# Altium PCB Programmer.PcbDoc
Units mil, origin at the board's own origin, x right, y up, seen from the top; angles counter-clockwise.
Board outline 2400 x 1200 mil, 2 copper layers (Top Layer, Bottom Layer); 47 components, 42 nets, 160 pads, 0 vias.
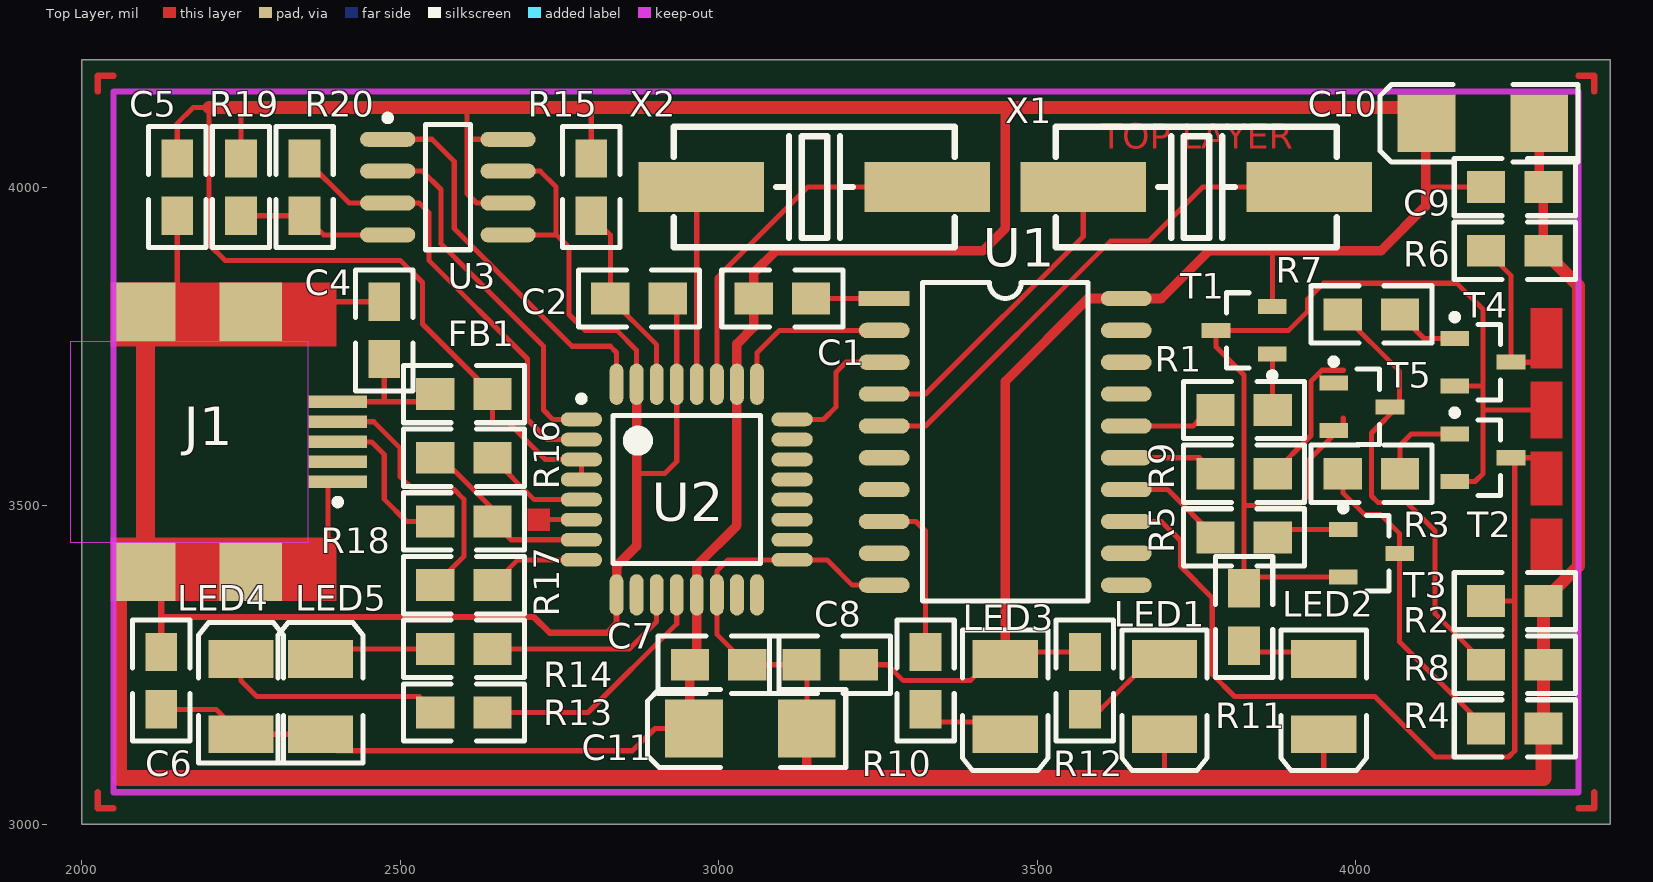
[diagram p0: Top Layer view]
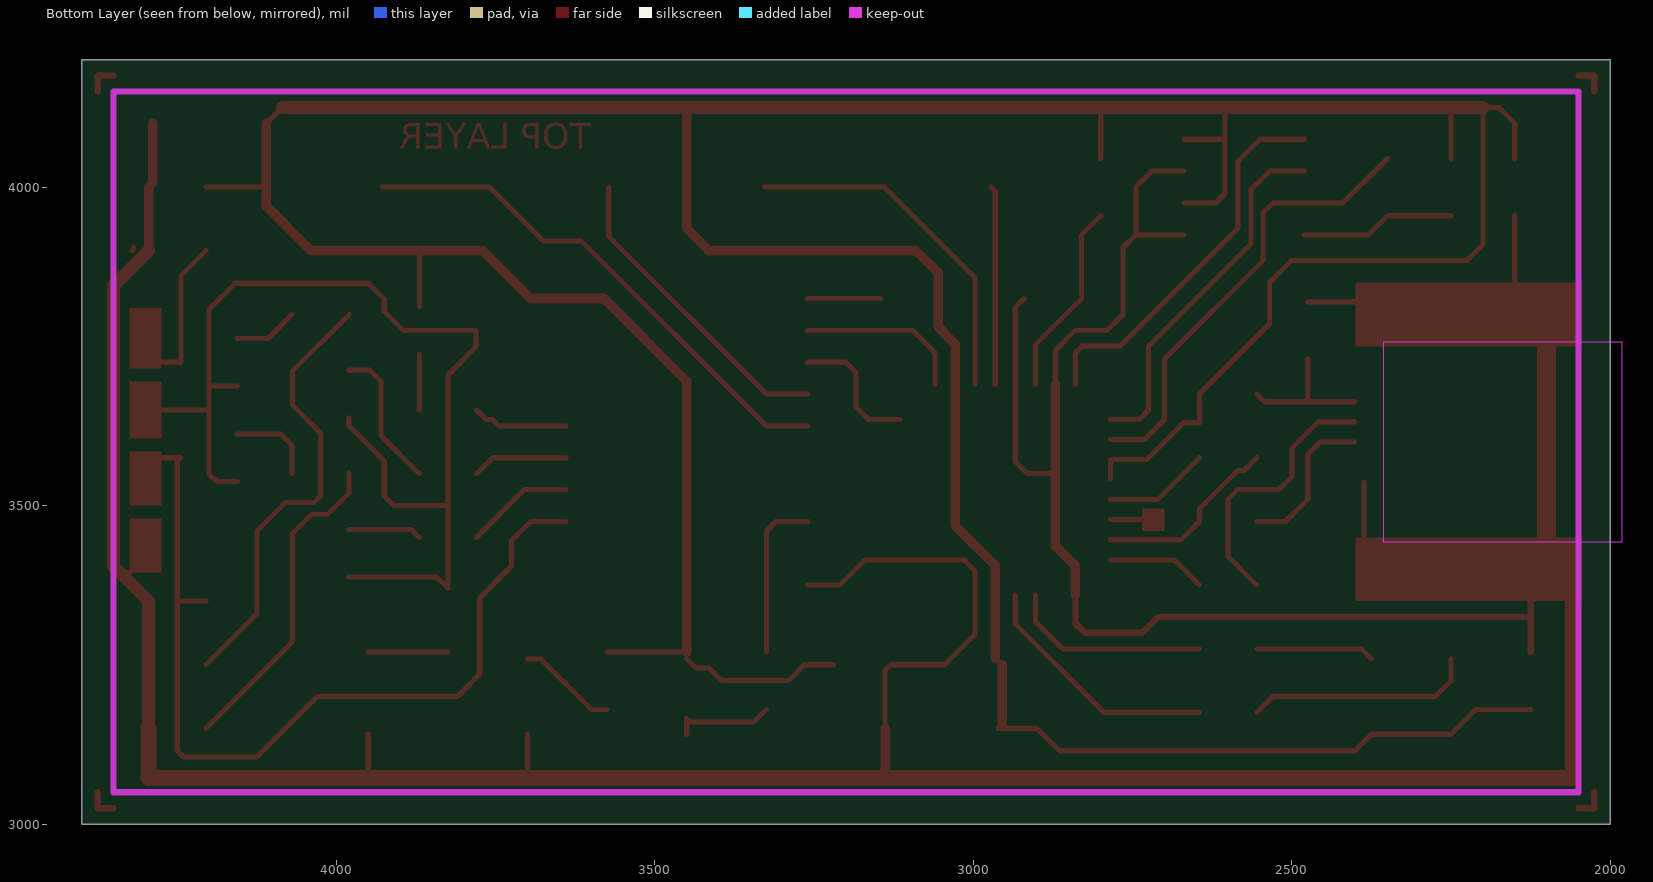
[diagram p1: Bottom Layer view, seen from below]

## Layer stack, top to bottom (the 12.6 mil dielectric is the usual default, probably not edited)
Top Layer: signal copper 1.4
Dielectric: dielectric 12.6, FR-4, Dk 4.8
Bottom Layer: signal copper 1.4

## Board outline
2000,3000 4400,3000 4400,4200 2000,4200

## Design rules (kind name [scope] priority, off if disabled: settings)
Clearance [All] p1: gap=8
PolygonConnect [All] p1: connectstyle=Relief reliefconductorwidth=10 reliefentries=4 polygonreliefangle="90 Angle"
RoutingVias [All] p1: holewidth=25 width=40 viastyle="Through Hole" minholewidth=28 minwidth=50 maxholewidth=28 maxwidth=50
SilkscreenOverComponentPads [All] p1: minsilkscreentomaskgap=10
SolderMaskExpansion [All] p1: expansion=4
Width [All] p1: maxlimit=8 minlimit=8 preferedwidth=8
27 further rules are at their usual default settings.

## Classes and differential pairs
component class Programmer: C1 C2 C4 FB1 LED1 LED2 LED3 LED4 LED5 R1 R2 R3 R4 R5 R6 R7 R8 R9 R10 R11 R12 R13 R14 R15 R16 R17 R18 R19 R20 T1 T2 T3 T4 T5 U1 U2 U3 X1 X2

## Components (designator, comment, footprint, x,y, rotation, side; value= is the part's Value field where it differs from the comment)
C1 "470n" 0805 3100,3825 r0 top
C2 "0.1u" 0805 2875,3825 r0 top
C4 "10n" 0805 2475,3775 r90 top
C5 "Comment" 0805 2150,4000 r90 top
C6 "Comment" 0805 2125,3225 r90 top
C7 "Comment" 0805 3000,3250 r180 top
C8 "Comment" 0805 3175,3250 r180 top
C9 "Comment" 0805 4250,4000 r180 top
C10 "Comment" SMB 4200,4100 r180 top
C11 "Comment" SMB 3050,3150 r180 top
FB1 "R" 0805 2600,3675 r180 top
J1 "0481900001" 481900001 2250,3600 r180 top
LED1 "LED3" 3.5X2.8X1.9 3700,3200 r270 top
LED2 "LED3" 3.5X2.8X1.9 3950,3200 r270 top
LED3 "LED3" 3.5X2.8X1.9 3450,3200 r270 top
LED4 "LED3" 3.5X2.8X1.9 2250,3200 r90 top
LED5 "LED3" 3.5X2.8X1.9 2375,3200 r90 top
R1 "1k" 0805 3825,3650 r0 top
R2 "10k" 0805 4250,3350 r0 top
R3 "1k" 0805 4025,3550 r180 top
R4 "1k" 0805 4250,3150 r0 top
R5 "1k" 0805 3825,3450 r0 top
R6 "10k" 0805 4250,3900 r0 top
R7 "1k" 0805 4025,3800 r0 top
R8 "1k" 0805 4250,3250 r0 top
R9 "1k" 0805 3825,3550 r0 top
R10 "470" 0805 3325,3225 r90 top
R11 "470" 0805 3825,3325 r270 top
R12 "470" 0805 3575,3225 r270 top
R13 "220" 0805 2600,3175 r180 top
R14 "220" 0805 2600,3275 r0 top
R15 "470" 0805 2800,4000 r270 top
R16 "1k5" 0805 2600,3575 r0 top
R17 "27" 0805 2600,3375 r0 top
R18 "27" 0805 2600,3475 r0 top
R19 "10k" 0805 2250,4000 r90 top
R20 "2k2" 0805 2350,4000 r90 top
T1 "PNP" SOT-23_N 3825,3775 r180 top
T2 "PNP" SOT-23B_N 4200,3575 r0 top
T3 "PNP" SOT-23B_N 4025,3425 r0 top
T4 "PNP" SOT-23B_N 4200,3725 r0 top
T5 "PNP" SOT-23B_N 4010,3655 r0 top
U1 "89C1051" SOL20 3450,3600 r0 top
U2 "FT232BL" LQFP-32_N 2950,3525 r0 top
U3 "93C46A-E/SN" SOIC-SN8_N 2575,4000 r0 top
X1 "12MHz" HC49S_SMD 3750,4000 r180 top
X2 "6MHz" HC49S_SMD 3150,4000 r180 top

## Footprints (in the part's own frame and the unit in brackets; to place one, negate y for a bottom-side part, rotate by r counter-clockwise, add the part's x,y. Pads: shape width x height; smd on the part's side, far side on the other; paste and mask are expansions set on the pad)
3.5X2.8X1.9 [mm] "SM LED; 2 C-Bend Leads; Body 3.5 x 2.8 x 1.9 mm, inc leads (LxWxH typ)"
  rect 1.5x2.6 smd: 1(-1.5,0) 2(1.5,0)
  silkscreen extent -2.65,-1.7 2.95,1.7
0805 [mil]
  rect 60x50 smd: 1(-45,0) 2(45,0)
  silkscreen extent -95,-45 95,45
481900001 [mm] "Connector; USB Mini-B, Sinking Type, SM; 5 Position; Right Angle"
  rect 2.35x0.5 smd: 1(-3.862,1.6) 2(-3.862,0.8) 3(-3.862,0) 4(-3.862,-0.8) 5(-3.862,-1.6)
  rect 2.5x2.35 smd: MH1(-0.387,-5.175) MH2(3.863,-5.175) MH3(3.863,5.175) MH4(-0.387,5.175)
  Keep-Out Layer region: -2.687,-4 6.813,-4 6.813,4 -2.687,4
  silkscreen extent -3.99,2.28 -3.74,2.52, body extent -1.8,-3.84 6.8,3.86, height 0.35
HC49S_SMD [mm]
  rect 5x2 smd: 1(-4.508,0) 1(4.508,0)
  silkscreen extent -5.6,-2.4 5.6,2.4
LQFP-32_N [mm] "Thin QFP, 32-Leads, Body 7x7mm, Pitch 0.8mm, IPC Medium Density"
  oval 1.65x0.55 smd: 1(-4.2,2.8) 2(-4.2,2) 3(-4.2,1.2) 4(-4.2,0.4) 5(-4.2,-0.4) 6(-4.2,-1.2) 7(-4.2,-2) 8(-4.2,-2.8) 17(4.2,-2.8) 18(4.2,-2) 19(4.2,-1.2) 20(4.2,-0.4) 21(4.2,0.4) 22(4.2,1.2) 23(4.2,2) 24(4.2,2.8)
  oval 0.55x1.65 smd: 9(-2.8,-4.2) 10(-2,-4.2) 11(-1.2,-4.2) 12(-0.4,-4.2) 13(0.4,-4.2) 14(1.2,-4.2) 15(2,-4.2) 16(2.8,-4.2) 25(2.8,4.2) 26(2,4.2) 27(1.2,4.2) 28(0.4,4.2) 29(-0.4,4.2) 30(-1.2,4.2) 31(-2,4.2) 32(-2.8,4.2)
  silkscreen extent -4.32,-2.95 2.95,3.75, body extent -3.5,-3.5 3.5,3.5, height 1.6
SMB [mm] "DO-214-AA/SMB; 2 C-Bend Leads; Body 5.3 x 3.6 mm, inc. leads (LxW)"
  rect 2.3x2.3 smd: 1(-2.25,0) 2(2.25,0)
  silkscreen extent -3.8,-1.55 4.1,1.55
SOIC-SN8_N [mm] "SOIC, 8-Leads, Body 4.9x3.8mm, Pitch 1.27mm, IPC Medium Density"
  oval 2.2x0.6 smd: 1(-2.4,1.905) 2(-2.4,0.635) 3(-2.4,-0.635) 4(-2.4,-1.905) 5(2.4,-1.905) 6(2.4,-0.635) 7(2.4,0.635) 8(2.4,1.905)
  silkscreen extent -2.52,-2.5 0.9,2.88, body extent -2,-2.5 2,2.5, height 1.75
SOL20 [mil]
  rect 80x24 smd: 1(-190,225)
  oval 80x24 smd: 2(-190,175) 3(-190,125) 4(-190,75) 5(-190,25) 6(-190,-25) 7(-190,-75) 8(-190,-125) 9(-190,-175) 10(-190,-225) 11(190,-225) 12(190,-175) 13(190,-125) 14(190,-75) 15(190,-25) 16(190,25) 17(190,75) 18(190,125) 19(190,175) 20(190,225)
  silkscreen extent -130,-250 130,250
SOT-23_N [mm] "SOT23, 3-Leads, Body 2.9x1.3mm, Pitch 0.95mm, Lead Span 2.5mm, IPC Medium Density"
  rect 1.15x0.6 smd: 1(-1.125,0.95) 2(-1.125,-0.95) 3(1.125,0)
  silkscreen extent -1.25,-1.5 0.7,1.92, body extent -0.7,-1.5 0.7,1.5, height 1.1
SOT-23B_N [mm] "SOT23, 3-Leads, Body 2.9x1.3mm, Pitch 0.95mm, Lead Span 2.4mm, IPC Medium Density"
  rect 1.15x0.6 smd: 1(-1.125,0.95) 2(-1.125,-0.95) 3(1.125,0)
  silkscreen extent -1.25,-1.5 0.7,1.92, body extent -0.7,-1.5 0.7,1.5, height 1.14

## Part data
C1 C2 C4: library part C, "Kondensator"
FB1: "Rezystor"
J1: "USB On-The-Go (OTG) Mini-B Receptacle, Right Angle, SMT, 0.80mm (.031\") Pitch, Solder Tabs with Back Cover, Recessed Type"
LED1 LED2 LED3 LED4 LED5: "Typical BLUE SiC LED"
R1 R2 R3 R4 R5 R6 R7 R8 R9 R10 R11 R12 R13 R14 R15 R16 R17 R18 R19 R20: library part R, "Rezystor"
T1 T2 T3 T4 T5: "PNP Bipolar Transistor"
U1: "Pro (f) esor"
U2: "USB UART Asynchronous Serial Data Transfer Chip, LQFP-32, Pb-Free"
U3: "1K, 128x8-bit, 5.0V Microwire Serial EEPROM, 8-Pin SOIC 150mil, Extended Temperature"
X1 X2: library part XTAL, "Crystal Oscillator"

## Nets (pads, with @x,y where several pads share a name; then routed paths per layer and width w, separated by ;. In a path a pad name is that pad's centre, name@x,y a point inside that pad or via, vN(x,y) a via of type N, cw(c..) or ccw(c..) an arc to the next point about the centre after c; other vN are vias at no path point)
GND: C2.2 C4.2 C5.1 C6.2 C7.1 C8.2 C9.1 C10.1 C11.1 J1.1 J1.MH1 J1.MH2 J1.MH3 J1.MH4 LED1.2 LED2.2 R2.2 R4.2 R6.2 R8.2 U1.10 U2.9 U2.14 U2.17 U2.29 U2.31 U3.5 U3.7 | length 7556.2
  Top Layer w8: J1.MH3@2060,3358.33 J1.MH3 ; J1.MH3@2097.93,3430.52 J1.MH3 ; J1.MH2@2097.93,3769.48 J1.MH2 ; J1.MH3@2125,3369.19 J1.MH3 ; C5.1 2150,3815 2138.74,3803.74 J1.MH2 ; J1.MH1 J1.MH2 ; J1.MH4@2288,3373.52 J1.MH4 J1.MH3 ; 2387.05,3430 J1.1@2387.05,3537.01 ; 2397.5,3820 C4.2 ; U3.5 2745,3925 ; U3.7 2720,4025 2745,4000 2745,3925 ; 2871.26,3550 2915,3550 2934.25,3569.25 U2.29 2934.25,3810.75 C2.2 ; U2.31 2871.26,3743.74 2840,3775 2790,3775 2765,3800 2765,3905 2745,3925 ; 3135,3072 3138.58,3075.58 ; C11.1 3138.58,3241.42 C8.2 C7.1 2997.24,3297.76 U2.14 2997.24,3397.24 3014.76,3414.76 U2.17 3170.24,3414.76 3210,3375 U1.10 ; 3700,3072 LED1.2 ; 3950,3072 LED2.2 ; C9.1@4288.58,4006.42 C9.1 ; 4300,3450 4300,3420 4325,3395 4340,3395 ; R6.2@4318.53,3905.88 R6.2@4320,3900
  Top Layer w10: C6.2 2125,3325 ; J1.MH3@2125,3369.19 2125,3325 ; U2.9 2839.76,3314.76 2825,3300 2735,3300 2710,3325 2125,3325
  Top Layer w15: U2.9 2839.76,3404.76 2871.26,3436.26 2871.26,3550 U2.31 ; 3138.58,3075.58 C11.1 ; C9.1@4288.58,4006.42 C10.1 ; R6.2 C9.1
  Top Layer w20: R4.2 R8.2 R2.2 4350,3405 4350,3845 R6.2
  Top Layer w22: 2060,3072 J1.MH3@2060,3358.33
  Top Layer w25: 2060,3072 3135,3072 3700,3072 3950,3072 4295,3072 R4.2
NetC1_2: C1.2 U1.1 | length 115
  Top Layer w8: C1.2 U1.1
NetC2_1: C2.1 R15.2 U2.30 | length 307.2
  Top Layer w8: R15.2 2830,3925 C2.1 2902.76,3752.24 U2.30
NetC3_1: U2.6 | length 64.6
  Top Layer w8: 2720,3477.76 U2.6
NetC4_1: C4.1 FB1.2 J1.5 | length 224.9
  Top Layer w8: J1.5 2475,3662.99 ; C4.1 2475,3662.99 ; FB1.2 2542.99,3662.99 2475,3662.99
NetJ1_3: J1.3 R18.1 | length 245.7
  Top Layer w8: J1.3 2455,3600 2475,3580 2475,3510 2510,3475 R18.1
NetJ1_4: J1.4 R17.1 | length 428.3
  Top Layer w8: J1.4 2458.5,3631.5 2500,3590 2500,3545 2520,3525 2585,3525 2600,3510 2600,3420 R17.1
NetLED1_1: LED1.1 R12.2 | length 157.7
  Top Layer w8: R12.2 3600,3180 3679.06,3259.06 LED1.1
NetLED2_1: LED2.1 R11.2 | length 125
  Top Layer w8: R11.2@3825,3270 LED2.1@3950,3270
NetLED3_2: LED3.2 R10.1 | length 160.7
  Top Layer w8: R10.1 3345,3160 3444.06,3160 3450,3165.94 LED3.2
NetLED4_2: LED4.2 R13.2 | length 359.8
  Top Layer w8: LED4.2 2250,3225 2275,3200 2530,3200 R13.2
NetLED5_2: LED5.2 R14.1 | length 186.6
  Top Layer w8: LED5.2 2390.94,3275 R14.1
NetR1_1: R1.1 U1.16 | length 150.4
  Top Layer w8: U1.16 3745,3625 3755,3635 3765,3635 R1.1
NetR1_2: R1.2 T1.1 | length 87.9
  Top Layer w8: T1.1 3869.29,3650.71 R1.2
NetR2_1: R2.1 T2.3 U1.13 | length 1424.2
  Top Layer w8: U1.13 3695,3475 3725,3445 3725,3405 3775,3355 3775,3235 3810,3200 4030,3200 4125,3105 4240,3105 4250,3115 4250,3350 ; R2.1 4250,3350 ; 4300,3575 T2.3 4250,3569.29 4250,3350
NetR3_1: R3.1 T2.1 | length 137.9
  Top Layer w8: R3.1 4070,3595 4087.4,3612.4 T2.1
NetR3_2: R3.2 R4.1 T3.3 | length 507.8
  Top Layer w8: R3.2 3980,3520 4013.79,3486.21 4038.79,3486.21 4069.29,3455.71 T3.3 4069.29,3285.71 R4.1
NetR5_1: R5.1 U1.14 | length 171.1
  Top Layer w8: U1.14 3705,3525 R5.1
NetR5_2: R5.2 T3.1 | length 115.8
  Top Layer w8: R5.2 3882.4,3462.4 T3.1
NetR6_1: R6.1 T4.3 | length 247
  Top Layer w8: R6.1 4244.29,3860.71 T4.3 4300,3725
NetR7_1: R7.1 R8.1 T5.3 | length 706.3
  Top Layer w8: R7.1 4069.29,3710.71 4069.29,3675 4069.29,3658.21 4025,3613.92 4025,3515 4035,3505 4080,3505 4125,3460 4125,3330 R8.1
NetR7_2: R7.2 T4.1 | length 101.3
  Top Layer w8: R7.2 4107.6,3762.4 T4.1
NetR9_1: R9.1 U1.15 | length 150.4
  Top Layer w8: U1.15 3755,3575 R9.1
NetR9_2: R9.2 T5.1 | length 227.8
  Top Layer w8: R9.2 3930,3610 3930,3695 3947.4,3712.4 3980.71,3712.4
NetR10_2: R10.2 U1.8 | length 261.2
  Top Layer w8: U1.8 3310,3475 3325,3460 R10.2
NetR11_1: R11.1 T1.3 T2.2 T3.2 T4.2 T5.2 | length 1769
  Top Layer w8: T3.2 3842.6,3387.6 R11.1 3825,3500 ; 3980.71,3637.6 3980.71,3625.71 3925,3570 3925,3515 3910,3500 3825,3500 ; T2.2 4187.6,3537.6 4200,3550 4200,3650 ; T4.2 4197.6,3687.6 4200,3690 ; 4300,3650 4200,3650 ; 3825,3500 3825,3705 3780.71,3749.29 T1.3 3895,3775 3925,3805 3925,3824 3950,3849 4159,3849 4200,3808 4200,3690 ; 4200,3650 4200,3690
NetR13_1: R13.1 U2.12 | length 392.3
  Top Layer w8: R13.1 2795,3175 2934.25,3314.25 U2.12
NetR14_2: R14.2 U2.11 | length 317.4
  Top Layer w8: R14.2 2860,3275 2902.76,3317.76 U2.11
NetR16_1: R16.1 R18.2 U2.7 | length 294.7
  Top Layer w8: R16.1 2575,3555 2585,3555 2645,3495 R18.2 2673.74,3446.26 U2.7
NetR16_2: R16.2 U2.5 | length 166.9
  Top Layer w8: R16.2 2710.75,3509.25 U2.5
NetR17_2: R17.2 U2.8 | length 156.1
  Top Layer w8: R17.2 2684.76,3414.76 U2.8
NetR19_1: R19.1 R20.1 U3.4 | length 242.9
  Top Layer w8: R19.1 R20.1 2380,3925 U3.4
NetR20_2: R20.2 U2.2 U3.3 | length 717
  Top Layer w8: R20.2 2420,3975 U3.3 2530,3975 2545,3960 2545,3885 2700,3730 2700,3635 2731.26,3603.74 U2.2
NetU1_2: U1.2 U2.25 | length 263.8
  Top Layer w8: U2.25 3060.24,3739.76 3095.47,3775 U1.2
NetU1_3: U1.3 U2.24 | length 213.8
  Top Layer w8: U2.24 3164.76,3635.24 3184.53,3655 3184.53,3709.53 3200,3725 U1.3
NetU1_4: U1.4 X1.1@3572.5,4000 | length 492.5
  Top Layer w8: U1.4 3325,3675 3572.5,3922.5 X1.1@3572.5,4000
NetU1_5: U1.5 X1.1@3927.5,4000 | length 822.8
  Top Layer w8: U1.5 3325,3625 3615,3915 3675,3915 3760,4000 X1.1@3927.5,4000
NetU2_1: U2.1 U3.2 | length 573.9
  Top Layer w8: U3.2 2535,4025 2564,3996 2564,3911 2725,3750 2725,3650 2739.76,3635.24 U2.1
NetU2_27: U2.27 X2.1@3327.5,4000 | length 556.3
  Top Layer w8: U2.27 2997.24,3857.24 3140,4000 X2.1@3327.5,4000
NetU2_28: U2.28 X2.1@2972.5,4000 | length 312.4
  Top Layer w8: U2.28 2965.75,3993.25 X2.1@2972.5,4000
NetU2_32: U2.32 U3.1 | length 609.6
  Top Layer w8: U3.1 2550,4075 2585,4040 2585,3935 2770,3750 2830,3750 2839.76,3740.24 U2.32 U2.32@2840,3690.59
VCC: C1.1 C5.2 C6.1 C7.2 C8.1 C9.2 C10.2 C11.2 FB1.1 LED3.1 LED4.1 LED5.1 R12.1 R15.1 R19.2 T1.2 U1.20 U2.3 U2.4 U2.13 U2.26 U3.6 U3.8 | length 7649.2
  Top Layer w8: C6.1 2210.94,3180 LED4.1 LED5.1 2400.94,3115 2865,3115 2900,3150 C11.2 C11.2@2955,3156.42 ; C5.2 2150,4100 2175,4125 2200,4125 2200,3910 2225,3885 2500,3885 2535,3850 2535,3785 FB1.1 2645,3630 2670,3630 2727.76,3572.24 U2.3 U2.4 ; R19.2 2250,4125 ; 2595,4125 2605,4115 2605,4075 ; U3.6 2620,3975 2605,3990 2605,4075 ; U3.8 2605,4075 ; R15.1 2800,4125 ; C7.2 C7.2@2965.75,3260.75 ; C8.1 3265,3250 3290,3225 3395,3225 3415,3245 3435.95,3245 LED3.1 ; LED3.1@3450,3270 R12.1 ; 3865,3900 3869.29,3895.71 T1.2 ; C10.2@4085,4125 C10.2@4110,4100 ; 4110,4000 C9.2
  Top Layer w15: C11.2@2955,3156.42 C7.2 ; C7.2@2965.75,3260.75 U2.13 2965.75,3405.75 3028.74,3468.74 U2.26 3028.74,3753.74 3055,3780 C1.1 3055,3865 3090,3900 3415,3900 3450,3935 3450,4125 ; LED3.1@3450,3270 3450,3695 3580,3825 U1.20 3695,3825 3770,3900 3865,3900 4040,3900 4110,3970 4110,4000 C10.2@4110,4100
  Top Layer w20: 2200,4125 2250,4125 2595,4125 2800,4125 3450,4125 C10.2@4085,4125
pads on no net: J1.2 U1.6 U1.7 U1.9 U1.11 U1.12 U1.17 U1.18 U1.19 U2.10 U2.15 U2.16 U2.18 U2.19 U2.20 U2.21 U2.22 U2.23
copper on no net: | length 200
  Top Layer w10: 2025,3050 2025,3025 2050,3025 ; 2025,4150 2025,4175 2050,4175 ; 4350,3025 4375,3025 4375,3050 ; 4350,4175 4375,4175 4375,4150

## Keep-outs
Keep-Out Layer:
  lines w10: 2050,3050 4350,3050 4350,4150 2050,4150 2050,3050

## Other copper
Top Layer:
  rectangle net NetC3_1: 2700,3460 2735,3495
  rectangle net GND: 2045,3350 2400,3450
  rectangle: 2380,3810 2385,3825
  rectangle net GND: 2045,3750 2400,3850
  rectangle net GND: 2085,3396.26 2115,3803.74
  rectangle net NetR11_1: 4275,3605 4325,3695
  rectangle net NetR6_1: 4275,3715 4325,3810
  rectangle net NetR2_1: 4275,3500 4325,3585
  rectangle net GND: 4275,3395 4325,3480
  text "TOP LAYER" at 3600,4060 h40

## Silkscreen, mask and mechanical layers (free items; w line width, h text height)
Drill Drawing:
  text ".LEGEND" at 4600,3200 h60
  text "Drill Drawing." at 4600,3100 h60

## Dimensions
2050,3050 to 4350,3050 on Mechanical 1
2050,3050 to 2050,4150 on Mechanical 1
